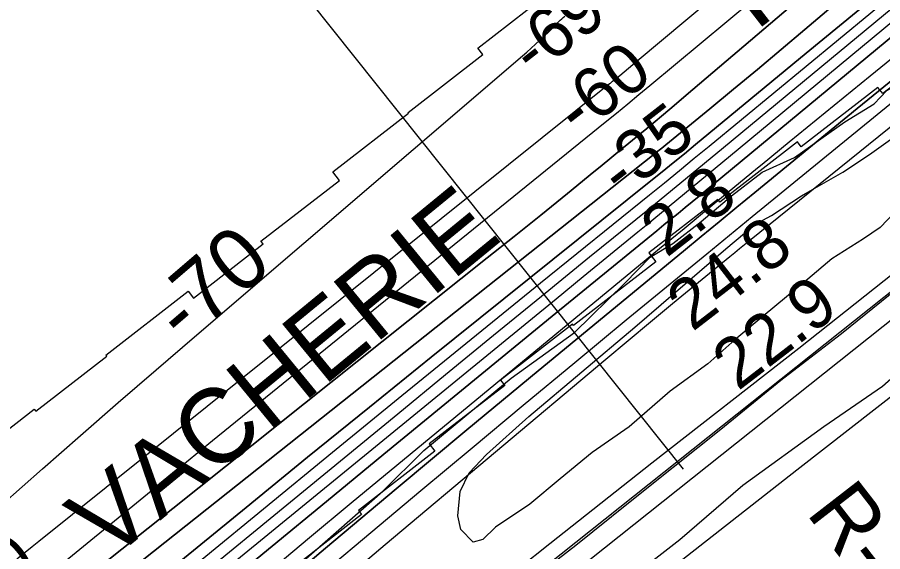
# Model space of a CAD drawing. Extents: x 3477039 to 3515015, y 546746 to 572297.
# Drawn here: x 3483194 to 3484351, y 556729 to 557444 of the extents above; entities that cross this region are included whole.
import ezdxf

# ---------------------------------------------------------------- set-up
doc = ezdxf.new("R2010")
doc.units = 0
for name, color, linetype in [('V-FLOD-BASE', 7, 'Continuous'), ('V-LEVE-TOET', 7, 'Continuous'), ('V-RIVR-EDGE', 7, 'Continuous'), ('V-RIVR-RANG', 7, 'Continuous'), ('V-RIVR-RANG-IDEN', 7, 'Continuous'), ('V-ROAD-CNTR', 7, 'Continuous'), ('V-RRAP-RVMT', 7, 'Continuous'), ('V-RRAP-RVMT-IDEN', 7, 'Continuous'), ('V-SITE-VEGE', 7, 'Continuous'), ('V-SURV-LINE', 7, 'Continuous'), ('V-TOPO-DPTH', 7, 'Continuous'), ('V-TOPO-MAJR', 7, 'Continuous'), ('V-TOPO-MINR', 7, 'Continuous'), ('V-TOPO-MINR-IDEN', 7, 'Continuous'), ('V-TOPO-WATR', 7, 'Continuous')]:
    doc.layers.add(name, color=color, linetype=linetype)

msp = doc.modelspace()

# ---------------------------------------------------------------- linework, layer by layer
at = {"layer": 'V-FLOD-BASE'}
msp.add_lwpolyline([(3484584.2, 557248.1), (3484473, 557160.1), (3484391.2, 557098), (3484296, 557020.8), (3484214.8, 556958.1), (3484134.4, 556892.5), (3484070.7, 556842), (3484011.2, 556794.2), (3483940.6, 556737.5), (3483875.5, 556687), (3483799.9, 556624.2), (3483711.8, 556555.2), (3483611.7, 556476.8), (3483550.1, 556427.6), (3483472.5, 556367.5), (3483388.5, 556299.9), (3483319.3, 556245.3), (3483258.4, 556198.9), (3483194, 556144.3), (3483180.7, 556133.4)], dxfattribs=at)
at = {"layer": 'V-LEVE-TOET'}
for points in [[(3483140.8, 556159.5), (3483158.3, 556171.7), (3483165.9, 556174.8), (3483178.5, 556179.8), (3483192.4, 556181), (3483207, 556185.7), (3483253.1, 556217), (3483386.1, 556325.6), (3483505, 556421.9), (3483623.3, 556515.4), (3483740.1, 556608.3), (3483905.9, 556740), (3484042.4, 556847.9), (3484238.9, 557001.4), (3484454.4, 557172.1), (3484582.4, 557271.7)], [(3484585.8, 557146.3), (3484433.9, 557023.3), (3484350.6, 556950.2), (3484272.3, 556896.4), (3484164, 556818), (3484079.9, 556744.9), (3484015.6, 556695), (3483932.3, 556629.5), (3483839.3, 556558.6), (3483743.5, 556482.1), (3483676.9, 556425.4), (3483601.3, 556360.5), (3483551, 556324.3), (3483476.9, 556269.1), (3483403.4, 556209), (3483350.2, 556166.7), (3483302.6, 556125), (3483259.1, 556084.6), (3483213, 556049.8), (3483163.2, 556005.4)]]:
    msp.add_lwpolyline(points, dxfattribs=at)
at = {"layer": 'V-RIVR-EDGE'}
msp.add_lwpolyline([(3483504.1, 556660.2), (3483576.2, 556716.7), (3483682.7, 556810.1), (3483737.5, 556864.6), (3483810.3, 556925.1), (3483854.2, 556961.6), (3483939, 557022.6), (3484006.4, 557088.5), (3484040.1, 557123.2), (3484070.2, 557141.7), (3484108.1, 557171.1), (3484149, 557205.2), (3484189.9, 557236.9), (3484233.1, 557256.6), (3484300.5, 557304.5), (3484339.6, 557328.4), (3484356.4, 557346.4), (3484391.3, 557365.5), (3484413.5, 557378), (3484434, 557388.2), (3484452.6, 557400.7), (3484487.5, 557429.5), (3484527.2, 557469)], dxfattribs=at)
at = {"layer": 'V-RIVR-RANG'}
msp.add_line((3484084.5, 556839.7), (3483585.7, 557465.2), dxfattribs=at)
at = {"layer": 'V-ROAD-CNTR'}
msp.add_lwpolyline([(3484980, 557432.6), (3484518.9, 557058.8), (3484236.1, 556838.3), (3484046.6, 556689.6), (3483814.6, 556500.6), (3483673.5, 556390.5), (3483557.4, 556297.9)], dxfattribs=at)
msp.add_lwpolyline([(3484980, 557432.6), (3484518.9, 557058.8), (3484236.1, 556838.3), (3484046.6, 556689.6), (3483814.6, 556500.6), (3483673.5, 556390.5), (3483557.4, 556297.9)], dxfattribs=at)
at = {"layer": 'V-RRAP-RVMT'}
for p, q in [((3484565.6, 557508.7), (3484351.1, 557342.1)), ((3483809.5, 557402.9), (3483919.8, 557488.4)), ((3483816.3, 557394.2), (3483809.5, 557402.9)), ((3483716.3, 557316.7), (3483816.3, 557394.2)), ((3484344.6, 557350.4), (3484242.2, 557271)), ((3484351.1, 557342.1), (3484344.6, 557350.4)), ((3483615.6, 557237.3), (3483716.9, 557315.9)), ((3483716.9, 557315.9), (3483716.3, 557316.7)), ((3484237.1, 557277.6), (3484133.2, 557197)), ((3484242.2, 557271), (3484237.1, 557277.6)), ((3483624.5, 557226), (3483615.6, 557237.3)), ((3483519.6, 557144.7), (3483624.5, 557226)), ((3484130.4, 557200.6), (3484038.2, 557129)), ((3484133.2, 557197), (3484130.4, 557200.6)), ((3483522.5, 557140.9), (3483519.6, 557144.7)), ((3483429.3, 557068.6), (3483522.5, 557140.9)), ((3484038.2, 557129), (3484047.5, 557117)), ((3484047.5, 557117), (3483937.4, 557031.7)), ((3483312, 556992.3), (3483422.2, 557077.7)), ((3483422.2, 557077.7), (3483429.3, 557068.6)), ((3483936, 557033.5), (3483839.9, 556958.9)), ((3483937.4, 557031.7), (3483936, 557033.5)), ((3483313.2, 556990.8), (3483312, 556992.3)), ((3483218.4, 556917.3), (3483313.2, 556990.8)), ((3483839.9, 556958.9), (3483845.5, 556951.6)), ((3483845.5, 556951.6), (3483744.7, 556873.4)), ((3483106.3, 556834.4), (3483216.4, 556919.9)), ((3483216.4, 556919.9), (3483218.4, 556917.3)), ((3483752.1, 556863.8), (3483649.8, 556784.4)), ((3483744.7, 556873.4), (3483752.1, 556863.8)), ((3483649.8, 556784.4), (3483654.1, 556778.9)), ((3483654.1, 556778.9), (3483543.9, 556693.3))]:
    msp.add_line(p, q, dxfattribs=at)
at = {"layer": 'V-SITE-VEGE'}
msp.add_lwpolyline([(3484367.3, 557183.4), (3484347.6, 557162.8), (3484325.2, 557147.7), (3484283.1, 557121.1), (3484250.8, 557093.7), (3484191, 557044.3), (3484153.1, 557012.7), (3484117.2, 556980.4), (3484066.6, 556944.2), (3484011.8, 556896.1), (3483962.7, 556861.9), (3483919.8, 556826.9), (3483879, 556792.6), (3483833.4, 556761.9), (3483816.5, 556745.4), (3483803.3, 556742.1), (3483786.8, 556759), (3483782.8, 556777.1), (3483786, 556809.8), (3483798.1, 556834.7), (3483821.4, 556859.4), (3483877.7, 556910.3), (3484019.7, 557029.6), (3484141.3, 557134.6), (3484180, 557166.9), (3484202.4, 557179.1), (3484242.4, 557205.1), (3484250.8, 557210), (3484297.7, 557237.1), (3484333.5, 557260.4), (3484397.3, 557306.2)], dxfattribs=at)
at = {"layer": 'V-SURV-LINE'}
for points in [[(3483197.5, 556150.5), (3484450.8, 557147.6)], [(3483197.5, 556150.5), (3484450.8, 557147.6)], [(3484469.5, 557124.1), (3483216.2, 556127)], [(3484469.5, 557124.1), (3483216.2, 556127)]]:
    msp.add_lwpolyline(points, dxfattribs=at)
at = {"layer": 'V-TOPO-DPTH'}
for points in [[(3483190.3, 556576), (3483211.5, 556594.4), (3483232.8, 556612.7), (3483254.2, 556630.8), (3483275.7, 556648.8), (3483297.4, 556666.6), (3483319.1, 556684.3), (3483341, 556701.9), (3483362.9, 556719.4), (3484045.2, 557260.9), (3484050.5, 557265), (3484055.7, 557269.2), (3484060.9, 557273.5), (3484066.1, 557277.7), (3484119.7, 557321.7), (3484151.6, 557348.1), (3484183.5, 557374.5), (3484215.2, 557401.1), (3484246.8, 557427.8), (3484857.9, 557946.2)], [(3484857.9, 557946.2), (3484246.8, 557427.8), (3484215.2, 557401.1), (3484183.5, 557374.5), (3484151.6, 557348.1), (3484119.7, 557321.7), (3484066.1, 557277.7), (3484060.9, 557273.5), (3484055.7, 557269.2), (3484050.5, 557265), (3484045.2, 557260.9), (3483362.9, 556719.4), (3483341, 556701.9), (3483319.1, 556684.3), (3483297.4, 556666.6), (3483275.7, 556648.8), (3483254.2, 556630.8), (3483232.8, 556612.7), (3483211.5, 556594.4), (3483190.3, 556576)], [(3484942.7, 557828.7), (3484926.3, 557815.5), (3484688.1, 557623.6), (3484595.1, 557548.5), (3484502.2, 557473.2), (3484409.6, 557397.7), (3484317, 557322.1), (3484180, 557209.7), (3484156.1, 557190.1), (3484132.2, 557170.5), (3484108.4, 557150.9), (3484084.5, 557131.3), (3483890.2, 556971.2), (3483795.1, 556892.4), (3483700.2, 556813.4), (3483605.8, 556733.8), (3483511.6, 556654), (3483352.1, 556517.9), (3483337.9, 556505.8), (3483323.9, 556493.6), (3483310, 556481.2), (3483296.1, 556468.8), (3483202.1, 556383.8), (3483141.3, 556328.9)], [(3483129.4, 556565.7), (3483200.3, 556625.7), (3483207.2, 556631.4), (3483214, 556637.2), (3483221, 556642.8), (3483228, 556648.4), (3483822.3, 557122.3), (3483858.1, 557150.9), (3483893.7, 557179.6), (3483929.3, 557208.4), (3483964.8, 557237.3), (3483973.2, 557244.2), (3484004.4, 557269.8), (3484035.4, 557295.5), (3484066.3, 557321.4), (3484097, 557347.4), (3484566, 557746.5)], [(3484566, 557746.5), (3484097, 557347.4), (3484066.3, 557321.4), (3484035.4, 557295.5), (3484004.4, 557269.8), (3483973.2, 557244.2), (3483964.8, 557237.3), (3483929.3, 557208.4), (3483893.7, 557179.6), (3483858.1, 557150.9), (3483822.3, 557122.3), (3483228, 556648.4), (3483221, 556642.8), (3483214, 556637.2), (3483207.2, 556631.4), (3483200.3, 556625.7), (3483129.4, 556565.7)], [(3483189.2, 556488.1), (3483255.8, 556546.5), (3483264.1, 556553.7), (3483272.4, 556560.9), (3483280.8, 556567.9), (3483289.2, 556574.9), (3483702.4, 556913.8), (3483766.5, 556966.3), (3483830.7, 557018.8), (3483894.9, 557071.2), (3483959.1, 557123.5), (3484036.9, 557186.7), (3484062.2, 557207.4), (3484087.5, 557228.2), (3484112.8, 557249), (3484138, 557269.8), (3484566.1, 557624.4)], [(3483189.2, 556488.1), (3483255.8, 556546.5), (3483264.1, 556553.7), (3483272.4, 556560.9), (3483280.8, 556567.9), (3483289.2, 556574.9), (3483702.4, 556913.8), (3483766.5, 556966.3), (3483830.7, 557018.8), (3483894.9, 557071.2), (3483959.1, 557123.5), (3484036.9, 557186.7), (3484062.2, 557207.4), (3484087.5, 557228.2), (3484112.8, 557249), (3484138, 557269.8), (3484566.1, 557624.4)], [(3484457.6, 557497.1), (3484124.3, 557220.5), (3484114.9, 557212.8), (3484105.5, 557205), (3484096.1, 557197.2), (3484086.7, 557189.5), (3484077.3, 557181.8), (3484067.9, 557174), (3484058.4, 557166.3), (3484049, 557158.6), (3483914.1, 557048.3), (3483837.3, 556985.4), (3483760.5, 556922.5), (3483683.8, 556859.5), (3483607.1, 556796.4), (3483389.2, 556616.9)], [(3483389.2, 556616.9), (3483607.1, 556796.4), (3483683.8, 556859.5), (3483760.5, 556922.5), (3483837.3, 556985.4), (3483914.1, 557048.3), (3484049, 557158.6), (3484058.4, 557166.3), (3484067.9, 557174), (3484077.3, 557181.8), (3484086.7, 557189.5), (3484096.1, 557197.2), (3484105.5, 557205), (3484114.9, 557212.8), (3484124.3, 557220.5), (3484457.6, 557497.1)], [(3484337.7, 557469.6), (3484248.9, 557396.2), (3484100.6, 557273.9), (3484085.8, 557261.7), (3484071, 557249.6), (3484056.1, 557237.5), (3484041.1, 557225.4), (3483747.2, 556989.3), (3483664.5, 556922.5), (3483581.9, 556855.6), (3483499.6, 556788.3), (3483417.5, 556720.9), (3483294.3, 556619.2), (3483274, 556602.3), (3483253.7, 556585.3), (3483233.7, 556568), (3483213.8, 556550.7), (3482979.7, 556345)], [(3484337.7, 557469.6), (3484248.9, 557396.2), (3484100.6, 557273.9), (3484085.8, 557261.7), (3484071, 557249.6), (3484056.1, 557237.5), (3484041.1, 557225.4), (3483747.2, 556989.3), (3483664.5, 556922.5), (3483581.9, 556855.6), (3483499.6, 556788.3), (3483417.5, 556720.9), (3483294.3, 556619.2), (3483274, 556602.3), (3483253.7, 556585.3), (3483233.7, 556568), (3483213.8, 556550.7), (3482979.7, 556345)]]:
    msp.add_lwpolyline(points, dxfattribs=at)
at = {"layer": 'V-TOPO-MAJR'}
msp.add_lwpolyline([(3483174.3, 556646.9), (3483193.9, 556663.5), (3483213.6, 556680), (3483233.4, 556696.4), (3483367.7, 556806.6), (3483454.9, 556877.9), (3483542.1, 556949), (3483629.4, 557020), (3483716.8, 557090.9), (3483979.9, 557303.8), (3483994.9, 557316), (3484010, 557328.3), (3484024.9, 557340.7), (3484039.8, 557353.1), (3484176.9, 557467.5)], dxfattribs=at)
at = {"layer": 'V-TOPO-MINR'}
for points in [[(3483185.9, 556713.2), (3483195, 556720.8), (3483204.2, 556728.5), (3483213.4, 556736), (3483222.7, 556743.5), (3483985.9, 557355.4), (3483986.8, 557356.2), (3483988.7, 557357.7), (3483989.6, 557358.5), (3483999.4, 557366.5), (3484005.2, 557371.3), (3484011, 557376), (3484016.8, 557380.8), (3484022.5, 557385.7), (3484795.8, 558032.6), (3484798.5, 558034.8), (3484801.2, 558037.1), (3484803.9, 558039.4), (3484806.6, 558041.6), (3484822.7, 558055.2), (3484833.4, 558064.2)], [(3483190.3, 556576), (3483211.5, 556594.4), (3483232.8, 556612.7), (3483254.2, 556630.8), (3483275.7, 556648.8), (3483297.4, 556666.6), (3483319.1, 556684.3), (3483341, 556701.9), (3483362.9, 556719.4), (3484045.2, 557260.9), (3484050.5, 557265), (3484055.7, 557269.2), (3484060.9, 557273.5), (3484066.1, 557277.7), (3484119.7, 557321.7), (3484151.6, 557348.1), (3484183.5, 557374.5), (3484215.2, 557401.1), (3484246.8, 557427.8), (3484857.9, 557946.2)], [(3483090.1, 556309.6), (3483264.9, 556471.2), (3483287.3, 556491.7), (3483309.8, 556512), (3483332.5, 556532.2), (3483355.3, 556552.2), (3483418.9, 556607.3), (3483473.8, 556654.6), (3483528.9, 556701.6), (3483584.4, 556748.2), (3483640.1, 556794.5), (3484052.7, 557134.8), (3484085.4, 557161.7), (3484118.1, 557188.7), (3484150.8, 557215.7), (3484183.6, 557242.6), (3484190, 557247.9), (3484226, 557277.4), (3484262, 557306.9), (3484298, 557336.4), (3484334.1, 557365.8), (3484890.9, 557819.1), (3484917.1, 557840.2), (3484943.3, 557861.3)], [(3483141.3, 556328.9), (3483202.1, 556383.8), (3483296.1, 556468.8), (3483310, 556481.2), (3483323.9, 556493.6), (3483337.9, 556505.8), (3483352.1, 556517.9), (3483511.6, 556654), (3483605.8, 556733.8), (3483700.2, 556813.4), (3483795.1, 556892.4), (3483890.2, 556971.2), (3484084.5, 557131.3), (3484108.4, 557150.9), (3484132.2, 557170.5), (3484156.1, 557190.1), (3484180, 557209.7), (3484317, 557322.1), (3484409.6, 557397.7), (3484502.2, 557473.2), (3484595.1, 557548.5), (3484688.1, 557623.6), (3484926.3, 557815.5), (3484942.7, 557828.7)], [(3483190.7, 556468.6), (3483205.4, 556482.5), (3483220.2, 556496.3), (3483235.2, 556509.8), (3483250.4, 556523.2), (3483274.9, 556544.7), (3483277.9, 556547.2), (3483280.9, 556549.8), (3483283.9, 556552.3), (3483286.9, 556554.8), (3483877.7, 557037.8), (3483914.2, 557067.6), (3483950.6, 557097.4), (3483987.1, 557127.2), (3484023.5, 557157.1), (3484034.7, 557166.2), (3484065.5, 557191.5), (3484096.3, 557216.8), (3484127.1, 557242.2), (3484157.8, 557267.7), (3484757.8, 557765.6)], [(3483129.4, 556565.7), (3483200.3, 556625.7), (3483207.2, 556631.4), (3483214, 556637.2), (3483221, 556642.8), (3483228, 556648.4), (3483822.3, 557122.3), (3483858.1, 557150.9), (3483893.7, 557179.6), (3483929.3, 557208.4), (3483964.8, 557237.3), (3483973.2, 557244.2), (3484004.4, 557269.8), (3484035.4, 557295.5), (3484066.3, 557321.4), (3484097, 557347.4), (3484566, 557746.5)], [(3483189.2, 556488.1), (3483255.8, 556546.5), (3483264.1, 556553.7), (3483272.4, 556560.9), (3483280.8, 556567.9), (3483289.2, 556574.9), (3483702.4, 556913.8), (3483766.5, 556966.3), (3483830.7, 557018.8), (3483894.9, 557071.2), (3483959.1, 557123.5), (3484036.9, 557186.7), (3484062.2, 557207.4), (3484087.5, 557228.2), (3484112.8, 557249), (3484138, 557269.8), (3484566.1, 557624.4)], [(3483185.6, 556343.4), (3483215.6, 556370.3), (3483245.7, 556397.2), (3483275.8, 556424), (3483323.7, 556466.4), (3483329.9, 556471.9), (3483336.3, 556477.4), (3483342.6, 556482.8), (3483349, 556488.2), (3483733.4, 556810.9), (3483801.8, 556868.2), (3483870.4, 556925.4), (3483939.2, 556982.3), (3484008.1, 557039.2), (3484115.8, 557127.8), (3484130.9, 557140.2), (3484146.1, 557152.6), (3484161.2, 557165.1), (3484176.4, 557177.5), (3484634.5, 557551.9)], [(3483644.8, 556703.9), (3483685.7, 556738.7), (3483981, 556987), (3484010.6, 557011.9), (3484040.3, 557036.6), (3484070.1, 557061.3), (3484099.9, 557085.9), (3484146.6, 557124.3), (3484153.2, 557129.7), (3484159.7, 557135), (3484166.3, 557140.4), (3484172.8, 557145.7), (3484680.1, 557555.5)], [(3483123.8, 556450.5), (3483235.4, 556548.6), (3483249.3, 556560.7), (3483263.4, 556572.7), (3483277.5, 556584.6), (3483291.7, 556596.4), (3483523.1, 556786.7), (3483615.4, 556862.5), (3483707.9, 556938.1), (3483800.6, 557013.5), (3483893.4, 557088.8), (3484039, 557206.5), (3484059.1, 557222.8), (3484079.1, 557239.1), (3484099, 557255.5), (3484119, 557271.9), (3484378.5, 557486.4)], [(3482979.7, 556345), (3483213.8, 556550.7), (3483233.7, 556568), (3483253.7, 556585.3), (3483274, 556602.3), (3483294.3, 556619.2), (3483417.5, 556720.9), (3483499.6, 556788.3), (3483581.9, 556855.6), (3483664.5, 556922.5), (3483747.2, 556989.3), (3484041.1, 557225.4), (3484056.1, 557237.5), (3484071, 557249.6), (3484085.8, 557261.7), (3484100.6, 557273.9), (3484248.9, 557396.2), (3484337.7, 557469.6)], [(3483172.9, 556791.9), (3483227.6, 556840.1), (3483278.2, 556884.5), (3483328.8, 556928.7), (3483379.6, 556972.7), (3483430.6, 557016.5), (3483869.2, 557392.6), (3483875, 557397.7), (3483880.8, 557402.8), (3483886.5, 557408), (3483892.2, 557413.3), (3483894.1, 557415), (3483898.8, 557419.5), (3483903.5, 557423.9), (3483908.1, 557428.4), (3483912.7, 557433), (3483918, 557438.4), (3483919.9, 557440.2), (3483921.9, 557442), (3483923.9, 557443.8), (3483925.9, 557445.5)]]:
    msp.add_lwpolyline(points, dxfattribs=at)
at = {"layer": 'V-TOPO-WATR'}
msp.add_lwpolyline([(3483389.2, 556616.9), (3483607.1, 556796.4), (3483683.8, 556859.5), (3483760.5, 556922.5), (3483837.3, 556985.4), (3483914.1, 557048.3), (3484049, 557158.6), (3484058.4, 557166.3), (3484067.9, 557174), (3484077.3, 557181.8), (3484086.7, 557189.5), (3484096.1, 557197.2), (3484105.5, 557205), (3484114.9, 557212.8), (3484124.3, 557220.5), (3484457.6, 557497.1)], dxfattribs=at)

# ---------------------------------------------------------------- texts
at = {"layer": 'V-RIVR-RANG'}
for s, rotation, p in [('-69', 37.9073, (3483884, 557363.5)), ('-60', 37.9073, (3483944.4, 557283.8)), ('-35', 37.9073, (3484002.1, 557202)), ('2.8', 37.9073, (3484061.9, 557121.8)), ('24.8', 37.6283, (3484096.5, 557022.7)), ('22.9', 37.6283, (3484157.5, 556943.5)), ('-60', 37.5543, (3483121.8, 556627.7))]:
    msp.add_text(s, height=67, rotation=rotation, dxfattribs=at).set_placement(p)
at = {"layer": 'V-RIVR-RANG-IDEN'}
msp.add_text('R-147.4', height=83, rotation=307.7657, dxfattribs=at).set_placement((3484247.5, 556781))
at = {"layer": 'V-RRAP-RVMT-IDEN'}
for s, rotation, p in [('REVET.', 37.7778, (3484181.2, 557425)), ('VACHERIE', 39.352, (3483315.6, 556714))]:
    msp.add_text(s, height=100, rotation=rotation, dxfattribs=at).set_placement(p)
at = {"layer": 'V-TOPO-MINR-IDEN'}
msp.add_text('-70', height=83, rotation=40.6103, dxfattribs=at).set_placement((3483416.6, 557004.6))

doc.saveas('drawing.dxf')
